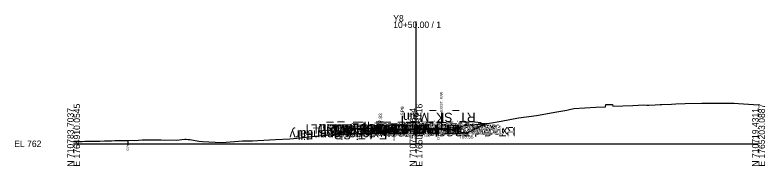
# Model space of a CAD drawing. Extents: x -26 to 1603, y -10 to 1060.
# Drawn here: x -25.7 to 302.8, y 490.3 to 556.2 of the extents above; entities that cross this region are included whole.
import ezdxf

# ---------------------------------------------------------------- set-up
doc = ezdxf.new("R2010")
doc.units = 0
for name, color, linetype in [('Default', 7, 'Continuous'), ('Exist CMT Pavement', 7, 'Continuous'), ('Exist Cross Section Cell', 7, 'Continuous'), ('Exist XS Center Line Elevation Label', 7, 'Continuous'), ('Exist XS Ground Line', 7, 'Continuous'), ('Old_Level_10', 7, 'Continuous'), ('Prop CMT Conc Surface', 7, 'Continuous'), ('Prop CMT Concrete Structures', 7, 'Continuous'), ('Prop CMT Pvmt Course 1', 7, 'Continuous'), ('Prop CMT Pvmt Course 1 CG', 7, 'Continuous'), ('Prop CMT Pvmt Course 2', 7, 'Continuous'), ('Prop CMT Pvmt Course 3', 7, 'Continuous'), ('Prop CMT Pvmt Surface', 7, 'Continuous'), ('Prop CMT Pvmt Surface Shoulder', 7, 'Continuous'), ('Prop CMT Shld Paved Course 1', 7, 'Continuous'), ('Prop CMT Shld Paved Course 3', 7, 'Continuous'), ('Prop CMT Slope Grass', 7, 'Continuous'), ('Prop CMT Subgrade Earthwork', 7, 'Continuous'), ('Prop XS Ditch Standard Text', 7, 'Continuous'), ('Prop XS Earthwork Shape', 7, 'Continuous'), ('Prop XS Hydro Elevations', 7, 'Continuous'), ('Prop XS SE Text', 7, 'Continuous'), ('Prop XS Shear Point Element', 7, 'Continuous'), ('Prop XS Side Slope Text', 7, 'Continuous'), ('Prop XS Wedging', 7, 'Continuous'), ('Scratch_Level_7', 7, 'Continuous')]:
    doc.layers.add(name, color=color, linetype=linetype)

msp = doc.modelspace()

# ---------------------------------------------------------------- linework, layer by layer
at = {"layer": 'Exist CMT Pavement'}
msp.add_lwpolyline([(140.41, 505.87), (141.03, 505.96), (141.99, 506.06), (142.6, 506.09), (144.55, 506.18), (145.88, 506.23), (147.11, 506.28), (149.16, 506.34), (150, 506.35), (150.55, 506.33), (151.48, 506.35), (152.23, 506.35), (154.19, 506.29), (154.79, 506.28), (155.72, 506.24), (157.35, 506.18), (157.92, 506.15), (159.36, 506.08), (159.73, 506.16)], dxfattribs=at)
at = {"layer": 'Exist Cross Section Cell'}
for p, q in [((150, 500), (150, 553.36)), ((0, 500), (150, 500)), ((150, 500), (300, 500))]:
    msp.add_line(p, q, dxfattribs=at)
at = {"layer": 'Exist XS Ground Line'}
msp.add_lwpolyline([(0, 500.95), (1.22, 500.98), (1.63, 500.99), (3.78, 501.04), (4.91, 501.06), (6.34, 501.08), (8.19, 501.13), (8.9, 501.15), (11.46, 501.18), (13.56, 501.25), (14.02, 501.26), (15.66, 501.29), (16.58, 501.32), (18.02, 501.35), (20.59, 501.41), (21.32, 501.43), (23.67, 501.48), (28.35, 501.53), (29.94, 501.64), (38.35, 501.67), (44.93, 501.62), (48.67, 502.03), (49.26, 502.02), (50.16, 501.85), (50.95, 501.81), (54.8, 501.1), (56.44, 501.02), (62.04, 500.67), (65.06, 500.6), (74.02, 501.22), (78.28, 501.28), (80.64, 501.47), (88.43, 501.83), (94.63, 502.2), (99.34, 502.55), (104.45, 503.14), (110.72, 503.74), (112.33, 503.85), (118.69, 504.19), (124.05, 504.45), (131.53, 504.66), (132.73, 504.63), (134.28, 504.5), (137.16, 505.05), (140.41, 505.87), (141.03, 505.96), (141.99, 506.06), (142.6, 506.09), (144.55, 506.18), (145.88, 506.23), (147.11, 506.28), (149.16, 506.34), (150, 506.35), (150.55, 506.33), (151.48, 506.35), (152.23, 506.35), (154.19, 506.29), (154.79, 506.28), (155.72, 506.24), (157.42, 506.18), (159.36, 506.08), (159.73, 506.16), (163.89, 505.87), (164.62, 506.09), (171.6, 508.06), (177.73, 508.49), (182.19, 508.96), (187.33, 509.92), (194.9, 511.3), (202.75, 512.4), (211.72, 514.01), (216, 514.72), (217.23, 515.01), (219.12, 515.35), (228.78, 515.93), (232.97, 516.17), (233.05, 517.21), (233.95, 517.2), (236.04, 517.2), (236.24, 516.38), (244.93, 516.75), (249.66, 516.93), (251.13, 516.9), (251.96, 516.87), (254.69, 517.04), (256.85, 517.14), (257.64, 517.18), (261.87, 517.32), (263.8, 517.41), (267.94, 517.58), (275.15, 517.75), (284.92, 517.77), (286.27, 517.79), (287.74, 517.74), (289.34, 517.69), (291.2, 517.58), (300, 517.05)], dxfattribs=at)
at = {"layer": 'Old_Level_10'}
for p, q in [((161.06, 513.6), (161.06, 506.2)), ((159.73, 506.16), (159.73, 504.11)), ((140.41, 505.87), (140.41, 503.82)), ((23.67, 501.48), (23.67, 499.43))]:
    msp.add_line(p, q, dxfattribs=at)
at = {"layer": 'Prop CMT Conc Surface'}
for points in [[(134.38, 505.93), (134.38, 506.43), (133.88, 506.43)], [(136.38, 506.07), (134.38, 505.93)]]:
    msp.add_lwpolyline(points, dxfattribs=at)
at = {"layer": 'Prop CMT Concrete Structures'}
for points in [[(136.38, 506.07), (134.38, 505.93), (134.38, 506.43), (133.88, 506.43)], [(133.88, 506.43), (133.88, 505.41), (136.38, 505.49)], [(136.38, 505.49), (136.38, 506.07)]]:
    msp.add_lwpolyline(points, dxfattribs=at)
at = {"layer": 'Prop CMT Pvmt Course 1'}
for points in [[(150, 506.53), (136.38, 506.07)], [(136.38, 506.07), (136.38, 505.82)], [(136.38, 505.82), (140.41, 505.96)], [(140.41, 505.96), (150, 506.28)], [(140.41, 505.96), (140.41, 505.96)], [(150, 506.53), (160, 506.86)], [(159.73, 506.6), (150, 506.28)], [(150, 506.28), (150, 506.53)], [(150, 506.28), (150, 506.28), (150, 506.28)], [(160, 506.61), (159.73, 506.6)], [(159.73, 506.6), (159.73, 506.6)], [(160, 506.86), (160, 506.61)]]:
    msp.add_lwpolyline(points, dxfattribs=at)
at = {"layer": 'Prop CMT Pvmt Course 1 CG'}
for points in [[(136.38, 505.49), (133.38, 505.39), (133.08, 505.09)], [(133.08, 505.09), (136.38, 505.2)], [(136.38, 505.2), (136.38, 505.49)]]:
    msp.add_lwpolyline(points, dxfattribs=at)
at = {"layer": 'Prop CMT Pvmt Course 2'}
for points in [[(140.41, 505.96), (136.38, 505.82)], [(140.41, 505.71), (140.41, 505.96)], [(159.73, 506.6), (160, 506.61)], [(136.38, 505.82), (136.38, 505.57)], [(136.38, 505.57), (140.41, 505.71)]]:
    msp.add_lwpolyline(points, dxfattribs=at)
at = {"layer": 'Prop CMT Pvmt Course 3'}
for points in [[(159.73, 506.6), (160, 506.61)], [(159.73, 506.18), (159.73, 506.6)], [(160, 506.19), (159.73, 506.18)], [(160, 506.61), (160, 506.19)], [(140.41, 505.71), (136.38, 505.57)], [(136.38, 505.57), (136.38, 505.2)], [(136.38, 505.2), (140.41, 505.33)], [(140.41, 505.33), (140.41, 505.71)]]:
    msp.add_lwpolyline(points, dxfattribs=at)
at = {"layer": 'Prop CMT Pvmt Surface'}
for points in [[(150, 506.53), (136.38, 506.07)], [(150, 506.53), (160, 506.86)]]:
    msp.add_lwpolyline(points, dxfattribs=at)
at = {"layer": 'Prop CMT Pvmt Surface Shoulder'}
msp.add_lwpolyline([(160, 506.86), (160, 506.86)], dxfattribs=at)
at = {"layer": 'Prop CMT Shld Paved Course 1'}
for points in [[(160, 506.86), (160, 506.86)], [(160, 506.86), (160.26, 506.61)], [(160, 506.61), (160, 506.86)], [(160.26, 506.61), (160, 506.61)]]:
    msp.add_lwpolyline(points, dxfattribs=at)
at = {"layer": 'Prop CMT Shld Paved Course 3'}
for points in [[(160, 506.61), (160.26, 506.61), (160.68, 506.18)], [(160.68, 506.18), (160, 506.19)]]:
    msp.add_lwpolyline(points, dxfattribs=at)
at = {"layer": 'Prop CMT Slope Grass'}
msp.add_line((172, 504.55), (180.44, 508.77), dxfattribs=at)
for points in [[(133.88, 506.43), (124.38, 506.62), (113.57, 503.92)], [(160, 506.86), (164, 506.55), (172, 504.55)]]:
    msp.add_lwpolyline(points, dxfattribs=at)
at = {"layer": 'Prop CMT Subgrade Earthwork'}
for p, q in [((159.73, 506.18), (160, 506.19)), ((159.73, 506.16), (159.73, 506.18)), ((160, 506.19), (160.68, 506.18)), ((140.41, 505.33), (140.41, 505.87))]:
    msp.add_line(p, q, dxfattribs=at)
for points in [[(136.38, 505.2), (133.08, 505.09), (131.69, 506.47)], [(160.68, 506.18), (161.26, 506.76)], [(140.41, 505.33), (136.38, 505.2)]]:
    msp.add_lwpolyline(points, dxfattribs=at)
at = {"layer": 'Prop XS Earthwork Shape'}
for points in [[(113.57, 503.92), (118.69, 504.19), (124.05, 504.45), (131.53, 504.66), (132.73, 504.63), (134.28, 504.5), (137.16, 505.05), (137.95, 505.25), (136.38, 505.2), (133.08, 505.09), (131.69, 506.47), (124.38, 506.62)], [(157.42, 506.18), (159.36, 506.08), (157.92, 506.15), (157.35, 506.18), (155.72, 506.24)], [(161.26, 506.76), (164, 506.55), (165.2, 506.25), (164.62, 506.09), (163.89, 505.87), (159.73, 506.16), (159.73, 506.18), (160, 506.19), (160.68, 506.18)], [(165.2, 506.25), (171.6, 508.06), (177.73, 508.49), (180.44, 508.77), (172, 504.55)], [(137.95, 505.25), (140.41, 505.87), (140.41, 505.33)]]:
    msp.add_lwpolyline(points, close=True, dxfattribs=at)
at = {"layer": 'Prop XS Shear Point Element'}
msp.add_line((144.01, 506.33), (144.01, 512.21), dxfattribs=at)
at = {"layer": 'Prop XS Wedging'}
for p, q in [((141.3, 505.99), (140.41, 505.96)), ((140.41, 505.96), (140.41, 505.87)), ((140.41, 505.87), (141.03, 505.96)), ((141.03, 505.96), (141.3, 505.99)), ((156.32, 506.49), (152.23, 506.35)), ((155.72, 506.24), (156.08, 506.23)), ((156.08, 506.23), (156.32, 506.49)), ((156.32, 506.49), (156.08, 506.23)), ((156.08, 506.23), (157.35, 506.18)), ((159.73, 506.6), (156.32, 506.49)), ((159.73, 506.18), (159.73, 506.6)), ((159.73, 506.16), (159.73, 506.18))]:
    msp.add_line(p, q, dxfattribs=at)
for points in [[(152.23, 506.35), (152.23, 506.35)], [(152.23, 506.35), (154.19, 506.29), (154.79, 506.28), (155.72, 506.24)], [(157.35, 506.18), (157.92, 506.15), (159.36, 506.08), (159.73, 506.16)]]:
    msp.add_lwpolyline(points, dxfattribs=at)

# ---------------------------------------------------------------- texts
at = {"layer": 'Default'}
msp.add_text('-', height=0.0001, dxfattribs=at).set_placement((0, 500))
at = {"layer": 'Exist Cross Section Cell'}
for s, p in [('Y8', (140, 553.36)), ('10+50.00 / 1', (140, 550.56)), ('EL 762', (-26, 498.6))]:
    msp.add_text(s, height=2.8, dxfattribs=at).set_placement(p)
for s, p in [('E 1764910.0545', (2.8, 490)), ('E 1765056.5716', (152.8, 490)), ('E 1765203.0887', (302.8, 490)), ('N 710783.7037', (0, 490)), ('N 710751.5674', (150, 490)), ('N 710719.4311', (300, 490))]:
    msp.add_text(s, height=2.8, rotation=90, dxfattribs=at).set_placement(p)
at = {"layer": 'Exist XS Center Line Elevation Label'}
msp.add_text('768.35', height=1, dxfattribs=at).set_placement((147.95, 504.35))
at = {"layer": 'Old_Level_10'}
for s, height, p in [('EXIST. R/W', 1.181, (161.65, 513.9)), ('EOP', 0.787, (140.81, 501.43)), ('EOP', 0.787, (160.12, 501.71)), ('EOP', 0.787, (24.07, 497.04))]:
    msp.add_text(s, height=height, rotation=90, dxfattribs=at).set_placement(p)
at = {"layer": 'Prop XS Ditch Standard Text'}
msp.add_text('SP9', height=1.5, rotation=90, dxfattribs=at).set_placement((144.76, 512.36))
msp.add_text('766.55', height=1.5, dxfattribs=at).set_placement((168.81, 502.29))
at = {"layer": 'Prop XS Hydro Elevations'}
msp.add_text('767.93', height=1.5, rotation=90, dxfattribs=at).set_placement((135.13, 506.93))
at = {"layer": 'Prop XS SE Text'}
for p in [(152.38, 507.61), (140.57, 507.21)]:
    msp.add_text('0.033', height=1.5, rotation=1.9092, dxfattribs=at).set_placement(p)
at = {"layer": 'Prop XS Side Slope Text'}
for s, rotation, p in [('4:1', 14.0362, (117.64, 505.71)), ('4:1', 345.9638, (166.77, 506.72)), ('2:1', 25.8022, (174.98, 506.41))]:
    msp.add_text(s, height=1.5, rotation=rotation, dxfattribs=at).set_placement(p)
at = {"layer": 'Scratch_Level_7'}
for s, p in [('RT_SK_Main', (176.06, 513.53)), ('LT_Sub_Trench_Out_DLT', (163.72, 508.47)), ('LT_CSLP_Pnt', (141.76, 508.62)), ('LT_CG_Top_BOC', (154.79, 508.43)), ('LT_CG_Top_Face', (156.2, 508.43)), ('LT_PV1_OEOT', (154.01, 508.07)), ('RT_PV1_IEEOP', (169.32, 508.28)), ('LT_PV1_IEEOP', (168.82, 508.28)), ('RT_PV2_IEEOP', (170.33, 508.28)), ('LT_PV2_IEEOP', (169.82, 508.28)), ('PV1_PGL', (160.68, 508.53)), ('RT_PV1_OEEOP', (179.93, 508.6)), ('PV2_PGL', (161.68, 508.28)), ('RT_PS3_Shelf_Out', (185.7, 508.34)), ('RT_PV2_OEEOP', (180.94, 508.6)), ('RT_PV3_OEEOP', (180.97, 508.35)), ('RT_PV1_OEOT', (178.14, 508.86)), ('RT_PS1_OEOP', (178.41, 508.86)), ('RT_PV2_OEOT', (179.15, 508.61)), ('RT_PV3_OEOT', (179.18, 508.36)), ('RT_PS2_OEOP', (179.67, 508.61)), ('RT_PS3_OEOP', (179.96, 508.35)), ('RT_GS_OS_CTL', (184.12, 508.54)), ('RT_Slope_Fill', (182.35, 508.4)), ('Exterior Boundary', (137.35, 505.92)), ('LT_Slope_Fill', (130.84, 505.92)), ('LT_CG1_Shelf_Out', (156.11, 507.39)), ('LT_CG_Bot_BOC', (154.35, 507.41)), ('LT_CG_Top_Gut', (154.25, 507.93)), ('LT_Sub_OEOP', (151.26, 507.09)), ('LT_PV2_OEOT', (155.02, 507.82)), ('LT_PV3_OEOT', (155.05, 507.57)), ('LT_Sub_OEOT', (154.48, 507.2)), ('LT_CG_Bot_IE', (154.36, 507.49)), ('LT_PV1_OEEOP', (160.11, 507.96)), ('LT_PV2_OEEOP', (161.12, 507.96)), ('LT_PV3_OEEOP', (161.15, 507.71)), ('LT_Sub_OEEOP', (160.58, 507.33)), ('RT_Sub_Trench_Out', (187.34, 507.96)), ('RT_Sub_OEEOP', (180.4, 507.98)), ('RT_Sub_OEOT', (178.61, 507.99)), ('RT_Sub_OSS_DLT', (193.35, 507.25)), ('Exterior Boundary', (193.67, 507.25))]:
    msp.add_text(s, height=4, rotation=180, dxfattribs=at).set_placement(p)

doc.saveas('drawing.dxf')
